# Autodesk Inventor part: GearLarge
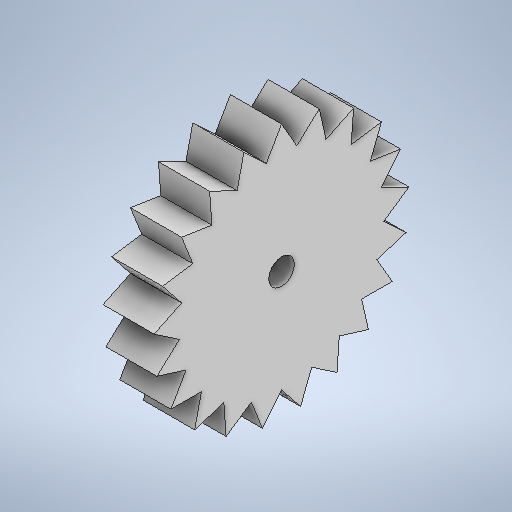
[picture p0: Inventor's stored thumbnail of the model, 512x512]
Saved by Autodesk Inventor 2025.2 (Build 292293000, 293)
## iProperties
Created: 2025-09
Part Number: GearLarge
Material: Generic
Document SubType Name: Modeling
Designer: tyler
Density: 1 g/cm^3
Appearance: Default
Author: tyler
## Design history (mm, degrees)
sketch "Sketch1"
  geometry: L1 (12.7, 0)-(15.875, 0); L2 (15.875, 0)-(12.554, -1.917); L3 (15.875, 0)-(12.554, 1.917); L4 (15.875, 0)-(19.709, 0); L5 (15.17, 4.679)-(11.432, 5.532); L6 (15.17, 4.679)-(12.562, 1.869); L7 (13.117, 8.943)-(9.293, 8.656); L8 (13.117, 8.943)-(11.453, 5.488); L9 (9.898, 12.412)-(6.329, 11.011); L10 (9.898, 12.412)-(9.326, 8.62); L11 (5.8, 14.778)-(2.802, 12.387); L12 (5.8, 14.778)-(6.371, 10.986); L13 (1.186, 15.831)-(-0.974, 12.663); L14 (1.186, 15.831)-(2.85, 12.376); L15 (-3.533, 15.477)-(-4.663, 11.813); L16 (-3.533, 15.477)-(-0.925, 12.666); L17 (-7.938, 13.748)-(-7.938, 9.914); L18 (-7.938, 13.748)-(-4.617, 11.831); L19 (-11.637, 10.798)-(-10.507, 7.134); L20 (-11.637, 10.798)-(-7.899, 9.945); L21 (-14.303, 6.888)-(-12.143, 3.72); L22 (-14.303, 6.888)-(-10.479, 7.174); L23 (-15.698, 2.366)-(-12.7, -0.025); L24 (-15.698, 2.366)-(-12.129, 3.767); L25 (-15.698, -2.366)-(-12.129, -3.767); L26 (-15.698, -2.366)-(-12.7, 0.025); L27 (-14.303, -6.888)-(-10.479, -7.174); L28 (-14.303, -6.888)-(-12.143, -3.72); L29 (-11.637, -10.798)-(-7.899, -9.945); L30 (-11.637, -10.798)-(-10.507, -7.134); L31 (-7.937, -13.748)-(-4.617, -11.831); L32 (-7.937, -13.748)-(-7.937, -9.914); L33 (-3.533, -15.477)-(-0.925, -12.666); L34 (-3.533, -15.477)-(-4.663, -11.813); L35 (1.186, -15.831)-(2.85, -12.376); L36 (1.186, -15.831)-(-0.974, -12.663); L37 (5.8, -14.778)-(6.371, -10.986); L38 (5.8, -14.778)-(2.802, -12.387); L39 (9.898, -12.412)-(9.326, -8.62); L40 (9.898, -12.412)-(6.329, -11.011); L41 (13.117, -8.943)-(11.453, -5.488); L42 (13.117, -8.943)-(9.293, -8.656); L43 (15.17, -4.679)-(12.562, -1.869); L44 (15.17, -4.679)-(11.432, -5.532); C1 r 1.587 at (0, 0); A1 r 12.7 centre (0, 0) between (12.7, 0) and (12.554, -1.917); 22 further points
  constraints: 88 end point, 3 point on circle, 2 centre point, 2 coincident, 2 horizontal, 1 equal length, 106 other
  dimensions: "d0" = 3.175 diameter of C1; "d1" = 25.4 diameter of A1; "d2" = 3.175 distance of L1.start L1.end; "d3" = 30 deg angle of L1 L2; "d4" = 150 deg angle of L4 L3; "d7" = 360 deg dimension on point (0, 0) L1.end (derived)
extrude "Extrusion1" new body sketch "Sketch1" distance "d9" = 6.35; taper "d10" = 0 deg
body "Solid1"
node "Sketch Circular Pattern1" dims "d7" = 360 deg (derived)
